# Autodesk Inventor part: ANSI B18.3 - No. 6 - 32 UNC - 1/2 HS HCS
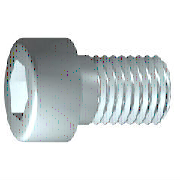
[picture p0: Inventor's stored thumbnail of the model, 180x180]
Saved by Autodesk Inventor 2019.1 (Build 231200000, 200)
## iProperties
Created: 2018-01
Part Number: ANSI B18.3 - No. 6 - 32 UNC - 1/2 HS HCS
Material: Steel, Mild
Description: Hexagon Socket Head Cap Screw
Document SubType Name: Modeling
Standard: ANSI B18.3
Designer: drawing
Standard Revision: 2003
Standards Organization: ANSI
Language: en-US
Size Designation: No. 6 - 32 UNC - 1/2
Categories: <MemberInstance><Categories><Category DisplayName="Fasteners" InternalName="e4da775c-781d-43d5-af7c-5136215cf5a6" Mnemonic="FSTN"><Category DisplayName="Bolts"
Density: 7.85 g/cm^3
Appearance: Semi-Polished
IsCustomPart: 0
Author: drawing
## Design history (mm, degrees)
sketch "Sketch1"
  geometry: L1 (-0.957, 0)-(12.7, 0); L2 (12.7, 0)-(12.7, 1.753); L3 (12.7, 1.753)-(1.984, 1.753); L4 (1.984, 1.753)-(0, 1.753); L5 (0, 1.753)-(0, 1.753); L6 (0, 1.753)-(0, 2.87); L7 (0, 2.87)-(-3.505, 2.87); L8 (-3.505, 2.87)-(-3.505, 1.598); L9 (-3.505, 1.598)-(-1.88, 1.598); L10 (-1.88, 1.598)-(-0.957, 0); L11 (-6.746, 0)-(15.941, 0) reference; L12 (0, -0.574)-(0, 3.444) reference; L13 (1.984, 1.753)-(0, 1.753)
  constraints: 22 end point, 6 parallel, 2 collinear, 2 perpendicular, 1 horizontal, 1 point on line
  dimensions: "d1" = 10.71555 distance from line of L3.end L2 (= GEL); "d2" = 1.98435 distance of L4.end L3.end (computed from GAL); "d3" = 3.5052 distance between parallel lines of L8 L6 (= KOH); "d4" = 1.6256 distance of L8.end L9.end (= INTI); "d5" = 60 deg angle of L10 L1; "d6" = 3.5052 diameter of L3 L1 (= GD); "d7" = 3.5052 diameter of L5 L1 (= BDM); "d8" = 3.1969 diameter of L9 L1 (= 1.1547 x SW); "d9" = 5.7404 diameter of L7 L1 (= KOD); "d26" = 12.7 distance between parallel lines of L12 L2 (= NLG)
revolve "Body" sketch "Sketch1" stored, may be unused: angle "d10" = 90 deg
sketch "Sketch2"
  geometry: L1 (0, -4.018)-(0, 4.018) reference; L2 (-4.018, 0)-(4.018, 0) reference; L3 (1.598, 0)-(0.799, -1.384); L4 (0.799, -1.384)-(-0.799, -1.384); L5 (-0.799, -1.384)-(-1.598, 0); L6 (-1.598, 0)-(-0.799, 1.384); L7 (-0.799, 1.384)-(0.799, 1.384); L8 (0.799, 1.384)-(1.598, 0); 2 further points
  constraints: 12 end point, 1 coincident, 1 horizontal alignment, 1 point on line, 12 other
extrude "Slot" join sketch "Sketch2" stored distance "d11" = 10; taper "d12" = 0 deg
workplane "Work Plane1"
fillet "Fillet2" dims "d30" = 0.127 (= R)
body "Solid1"
fillet "Fillet1" dims "d17" = 0.3302 (= RR)
feature "Thread" dims "d13" = 10.71555 (= GEL), "d14" = 0
chamfer "Chamfer1" distance "d15" = 0.47244 (= -0.5 x SPD + 0.5 x GD); stored, may be unused: second distance "d16" = 0.47244 (= GUL), angle "d27" = 45 deg
other parameters: "GD" = 3.5052 [user parameter; used in 2 equation terms], "NLG" = 12.7 [user parameter; used in 1 equation term], "GEL" = 10.71555 [user parameter; used in 2 equation terms], "KOD" = 5.7404 [user parameter; used in 1 equation term], "KOH" = 3.5052 [user parameter; used in 1 equation term], "INTI" = 1.6256 [user parameter; used in 1 equation term], "GAL" = 1.98425 [user parameter; used in 1 equation term], "GUL" = 0.47244 [user parameter; used in 1 equation term], "BDM" = 3.5052 [user parameter; used in 1 equation term], "SW" = 2.7686 [user parameter; used in 2 equation terms], "RR" = 0.3302 [user parameter; used in 1 equation term], "SPD" = 2.56032 [user parameter; used in 2 equation terms], "d19" = 0, "d28" = 0, "d29" = 0, "R" = 0.127 [user parameter; used in 1 equation term], "PHH" = 0.127 [user parameter], "GD1" = 2.56032 (= SPD) [user parameter], "THREADDIA" = 3.5052 [user parameter], "FAWI" = 45 deg [user parameter], "PTC" = 0.79375 (computed from TPU) [user parameter], "KOH1" = 3.1496 [user parameter], "NND" = 3.5052 [user parameter], "TOA" = 30 deg [user parameter], "E0" = 3.19773 (= 1.155 x SW) [user parameter]
